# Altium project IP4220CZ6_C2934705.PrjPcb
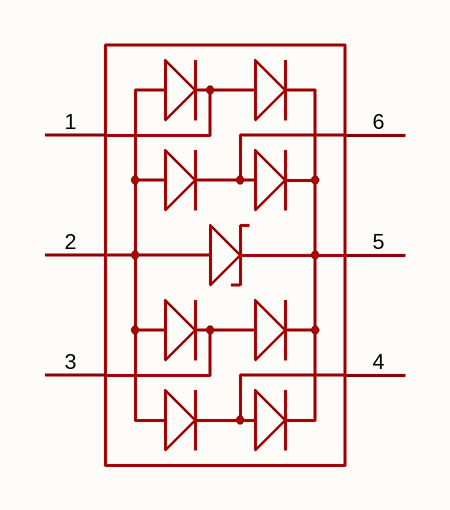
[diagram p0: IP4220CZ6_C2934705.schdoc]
1 sheet, 1 parts. Net scope: global (net labels, ports and power ports of the same name join across sheets).

## Sheet IP4220CZ6_C2934705.schdoc
size 127 x 101 mm

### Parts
U?  ip4220cz6_c2934705  [TSOP-6_L3.0-W1.5-P0.95-LS2.8-TL]  (value not drawn)

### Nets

Not connected (* = marked no-connect by the designer): U? 1 2 3 4 5 6

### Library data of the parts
U? = ip4220cz6_c2934705: 反向截止电压(Vrwm):5V;钳位电压:12V;峰值脉冲电流(Ipp):5A@8/20us;击穿电压(VBR):10V;; Manufacturer: JSMSEMI(杰盛微); AddInBom: yes; ModelId: 7f4a15aa106b47b6a6067b901007009d; ModelName: TSOP-6_L3.0-W1.5-H1.0-LS2.8-P0.95; ModelTransform: 114.645,110.236,0,0,0,0,0,0,0; Reverse Stand-Off Voltage (Vrwm): 5V; Clamping Voltage: 12V; Voltage - Breakdown: 10V; Reverse Leakage Current (Ir): 1uA; Number of Channels: 四路; level of protection: IEC 61000-4-2; Junction Capacitance: 0.75pF；0.35pF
